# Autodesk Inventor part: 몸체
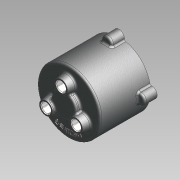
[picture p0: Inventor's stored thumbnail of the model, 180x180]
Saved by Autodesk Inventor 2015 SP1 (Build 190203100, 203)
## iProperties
Company: 한국ATC센터
Created: 2014-07
Part Number: 몸체
Document SubType Name: 모델링
Designer: KYOUNG IL JANG
Material: 알루미늄 6061
Appearance: 알루미늄 - 평지
Mass: 473.798 g
Surface Area: 687.661 cm^2
Volume: 175.481 cm^3
Density: 2.7 g/cm^3
변환 표준: STEP AP214IS
파일 이름: C:\Users\SeoGD\Desktop\?쒗뿕\紐몄껜.stp
전처리기: Build: 253, Release: 2010 SP1 - Date: Wed 07/29/2009
전송 단위: 밀리미터
불확실성: 0.01
Author: KYOUNG IL JANG
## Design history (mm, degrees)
sketch "스케치2"
  geometry: C1 r 50 at (0, 0); 1 further point
  constraints: 1 centre point, 1 coincident
  dimensions: "d9" = 100 diameter of C1
extrude "돌출2" new body sketch "스케치2" distance "d10" = 80; taper "d11" = 0 deg
feature "쉘1" dims "d12" = 5
sketch "스케치3" dims "d13" = 55
  geometry: C1 r 7.5 at (0, 27.5); C2 r 12.5 at (0, 27.5); 2 further points
  constraints: 2 centre point, 2 coincident, 2 vertical alignment, 2 other
  dimensions: "d14" = 15 diameter of C1; "d15" = 25 diameter of C2
extrude "돌출3" join sketch "스케치3" distance "d16" = 12; taper "d17" = -10 deg
hole "구멍2" diameter "d20" = 15; stored, may be unused: countersink angle "d24" = 90 deg, drill point angle "d26" = 118 deg; dims "d18" = 10, "d19" = 10, "d21" = 6, "d22" = 4, "d23" = 2, "d25" = 15
chamfer "모따기1" distance "d27" = 1; stored, may be unused: second distance "d28" = 2, angle "d29" = 45 deg
sketch "스케치4"
  geometry: L1 (0, 0)-(0, 88); L2 (0, 70)-(13.16, 70); L3 (-45, 75)-(45, 75) reference; L4 (-50, 80)-(50, 80) reference; L5 (13.16, 70)-(14.5, 75); L6 (20, 80)-(20, 88); L7 (20, 88)-(0, 88); L8 (20, 80)-(14.5, 75)
  constraints: 12 end point, 3 point on line, 2 perpendicular, 1 vertical
  dimensions: "d34" = 40 diameter of L6 L1; "d35" = 105 deg angle of L5 L3; "d36" = 5 distance between parallel lines of L2 L3; "d37" = 8 distance between parallel lines of L7 L4; "d51" = 29 diameter of L5.end L1
revolve "회전1" sketch "스케치4" stored, may be unused: angle "d38" = 90 deg
hole "구멍3" diameter "d41" = 15; stored, may be unused: countersink angle "d45" = 90 deg, drill point angle "d47" = 0 deg; dims "d39" = 10, "d40" = 10, "d42" = 6, "d43" = 22, "d44" = 13, "d46" = 15
chamfer "모따기2" distance "d48" = 1; stored, may be unused: second distance "d49" = 2, angle "d50" = 45 deg
fillet "모깎기1" dims "d52" = 3
fillet "모깎기2" dims "d53" = 3, "d72" = 0.2
sketch "스케치5"
  geometry: A1 r 50 centre (0, 0) between (50, 0) and (-8.074, 49.344) reference; A2 r 8.5 centre (0, 52) between (8.074, 49.344) and (-8.074, 49.344); 1 further point
  constraints: 5 point on circle, 1 centre point, 1 horizontal alignment
  dimensions: "d54" = 90 deg dimension on point (0, 0) A2.centre A1.start; "d55" = 52 distance of A2.centre point (0, 0); "d56" = 17 diameter of A2
extrude "돌출4" join sketch "스케치5" distance "d57" = 20; taper "d58" = 0 deg
fillet "모깎기3" dims "d59" = 3
hole "구멍4" diameter "d62" = 4.134; stored, may be unused: countersink angle "d66" = 90 deg, drill point angle "d68" = 118 deg; dims "d60" = 10, "d61" = 10, "d63" = 12, "d64" = 22, "d65" = 13, "d67" = 15
sketch "스케치6"
  geometry: C1 r 47 at (0, 0) reference; C2 r 42.5 at (0, 0); 1 further point
  constraints: 1 centre point, 1 coincident, 1 other
  dimensions: "d73" = 85 diameter of C2
feature "엠보싱1" sketch "스케치6" dims "d74" = 1, "d75" = 0
node "솔리드1"
node "솔리드 본체"
node "곡면 본체"
pattern_circular "원형 패턴1" dims "d31" = 360 deg
pattern_circular "원형 패턴2" dims "d70" = 360 deg
node "솔리드2"
